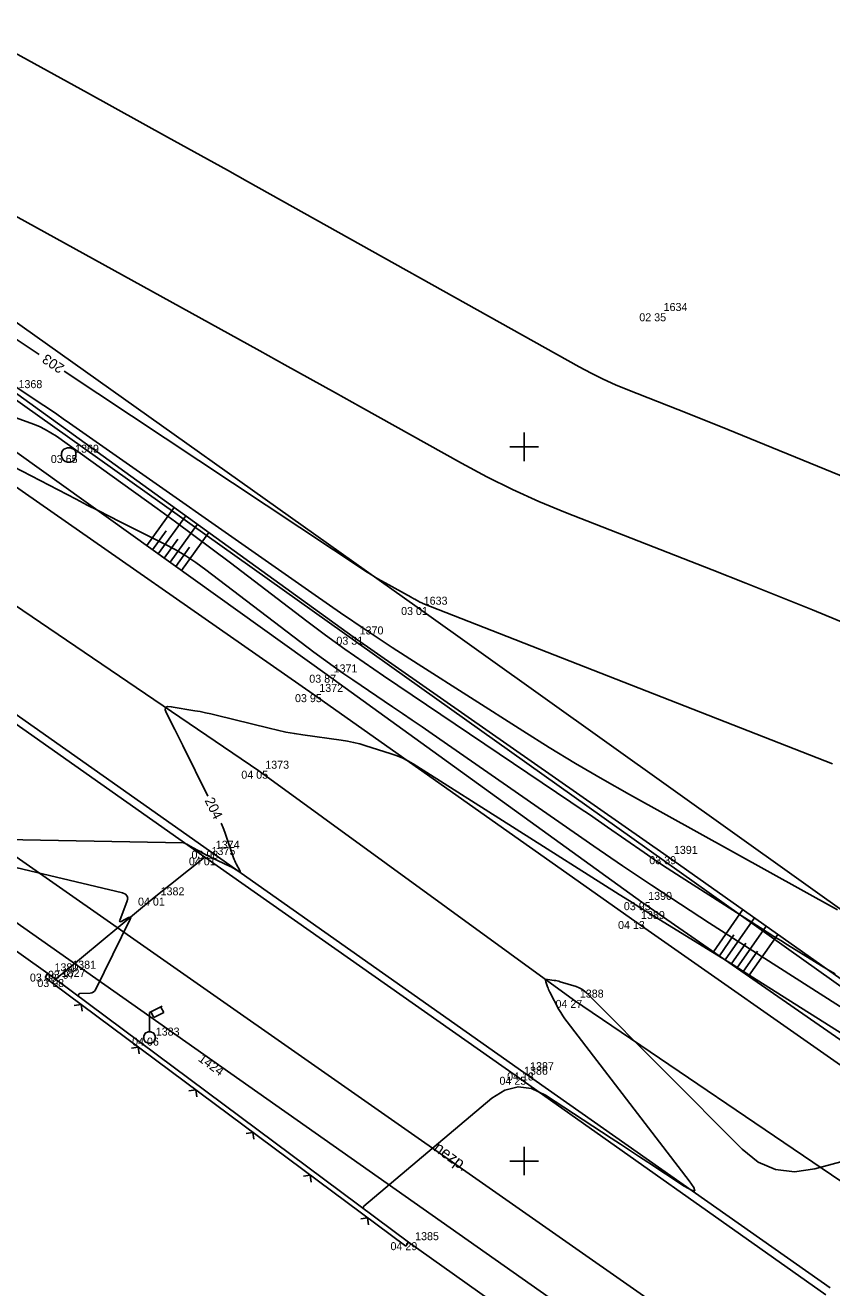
# Model space of a CAD drawing. Extents: x -711234 to -710007, y -1026313 to -1025448.
# Drawn here: x -710542.44 to -710514.24, y -1025579.43 to -1025535.25 of the extents above; entities that cross this region are included whole.
import ezdxf

# ---------------------------------------------------------------- set-up
doc = ezdxf.new("R2010")
doc.units = 0
for name, color, linetype in [('Ex_Contour Labels', 7, 'Continuous'), ('Ex_Major Contours', 7, 'Continuous'), ('Ex_Minor Contours', 7, 'Continuous'), ('Z_body', 7, 'Continuous'), ('Z_body_cisla', 7, 'Continuous'), ('Z_body_vysky_redukovane', 7, 'Continuous'), ('Z_hektometricka_sit', 7, 'Continuous'), ('Z_hrany_paty', 7, 'Continuous'), ('Z_katastr_cisla_pozemkova', 7, 'Continuous'), ('Z_katastr_hranice', 7, 'Continuous'), ('Z_komunikace', 7, 'Continuous'), ('Z_komunikace_osa', 7, 'Continuous'), ('Z_obruba', 7, 'Continuous'), ('Z_ploty', 7, 'Continuous'), ('Z_ploty_znacky', 7, 'Continuous'), ('Z_pole_rozhranni', 7, 'Continuous'), ('Z_popisy', 7, 'Continuous'), ('Z_rozhranni', 7, 'Continuous'), ('Z_site_kanalizace_znaky', 7, 'Continuous'), ('Z_site_vo_znaky', 7, 'Continuous'), ('Z_technicke_srafy', 7, 'Continuous'), ('Z_vstupy', 7, 'Continuous')]:
    doc.layers.add(name, color=color, linetype=linetype)

# ---------------------------------------------------------------- blocks, each defined once
blk = doc.blocks.new('POINT_DISPLAY')
blk.add_line((0, 0), (0, 0))
blk = doc.blocks.new('Z13')
for p, q in [((0, 0.88), (0.45, 1.1)), ((0.15, 0.7), (0.05, 0.9)), ((0.4, 1.07), (0.5, 0.88)), ((0, 0.2), (0, 0.88)), ((0.5, 0.88), (0.15, 0.7)), ((-0.2, 0.05), (-0.15, 0.15)), ((-0.2, -0.05), (-0.2, 0.05)), ((-0.15, 0.15), (-0.05, 0.2)), ((-0.05, 0.2), (0.05, 0.2)), ((0.05, 0.2), (0.15, 0.15)), ((0.15, 0.15), (0.2, 0.05)), ((0.2, 0.05), (0.2, -0.05)), ((-0.15, -0.15), (-0.2, -0.05)), ((-0.05, -0.2), (-0.15, -0.15)), ((0.05, -0.2), (-0.05, -0.2)), ((0.15, -0.15), (0.05, -0.2)), ((0.2, -0.05), (0.15, -0.15))]:
    blk.add_line(p, q)
blk = doc.blocks.new('Z212')
for p, q in [((-0.17, 0.17), (0, 0)), ((0, 0), (0.17, 0.17))]:
    blk.add_line(p, q)
blk = doc.blocks.new('Z620')
for p, q in [((-0.25, 0.05), (-0.23, 0.13)), ((-0.25, -0.05), (-0.25, 0.05)), ((-0.23, 0.13), (-0.17, 0.2)), ((-0.17, 0.2), (-0.05, 0.25)), ((-0.05, 0.25), (0.05, 0.25)), ((0.05, 0.25), (0.17, 0.2)), ((0.17, 0.2), (0.23, 0.13)), ((0.23, 0.13), (0.25, 0.05)), ((0.25, 0.05), (0.25, -0.05)), ((-0.2, -0.17), (-0.25, -0.05)), ((-0.13, -0.23), (-0.2, -0.17)), ((-0.05, -0.25), (-0.13, -0.23)), ((0.05, -0.25), (-0.05, -0.25)), ((0.13, -0.23), (0.05, -0.25)), ((0.2, -0.17), (0.13, -0.23)), ((0.25, -0.05), (0.2, -0.17))]:
    blk.add_line(p, q)

msp = doc.modelspace()

# ---------------------------------------------------------------- linework, layer by layer
at = {"layer": 'Ex_Major Contours'}
for points in [[(-710544.313, -1025545.208), (-710541.957, -1025546.772)], [(-710541.082, -1025547.353), (-710530.483, -1025554.386), (-710530.329, -1025554.486), (-710530.172, -1025554.584), (-710530.013, -1025554.677), (-710529.853, -1025554.768), (-710528.952, -1025555.265), (-710528.918, -1025555.284), (-710528.884, -1025555.303), (-710528.85, -1025555.322), (-710528.816, -1025555.341), (-710528.68, -1025555.416), (-710528.646, -1025555.435), (-710528.612, -1025555.452), (-710528.576, -1025555.468), (-710528.54, -1025555.483), (-710515.021, -1025560.786), (-710514.219, -1025561.103)], [(-710536.055, -1025562.233), (-710536.93, -1025560.46), (-710537, -1025560.318), (-710537.071, -1025560.177), (-710537.143, -1025560.035), (-710537.215, -1025559.894), (-710537.505, -1025559.33), (-710537.548, -1025559.21), (-710537.535, -1025559.132), (-710537.465, -1025559.095), (-710537.337, -1025559.101), (-710536.517, -1025559.238), (-710536.328, -1025559.271), (-710536.141, -1025559.308), (-710535.954, -1025559.349), (-710535.768, -1025559.394), (-710533.911, -1025559.855), (-710533.62, -1025559.924), (-710533.327, -1025559.985), (-710533.033, -1025560.038), (-710532.737, -1025560.083), (-710531.398, -1025560.27), (-710531.178, -1025560.305), (-710530.961, -1025560.35), (-710530.745, -1025560.403), (-710530.531, -1025560.465), (-710529.68, -1025560.732), (-710529.471, -1025560.805), (-710529.267, -1025560.892), (-710529.07, -1025560.991), (-710528.878, -1025561.104), (-710521.67, -1025565.667), (-710521.309, -1025565.895), (-710520.948, -1025566.121), (-710520.586, -1025566.346), (-710520.223, -1025566.57), (-710518.771, -1025567.464), (-710518.408, -1025567.688), (-710518.046, -1025567.912), (-710517.685, -1025568.139), (-710517.324, -1025568.366), (-710507.868, -1025574.338)], [(-710545.031, -1025563.71), (-710536.925, -1025563.86), (-710536.904, -1025563.862), (-710536.883, -1025563.866), (-710536.864, -1025563.873), (-710536.845, -1025563.883), (-710536.772, -1025563.927), (-710536.753, -1025563.938), (-710536.735, -1025563.948), (-710536.716, -1025563.959), (-710536.697, -1025563.969), (-710536.264, -1025564.207), (-710536.185, -1025564.25), (-710536.106, -1025564.291), (-710536.026, -1025564.331), (-710535.945, -1025564.371), (-710535.283, -1025564.688), (-710535.243, -1025564.707), (-710535.203, -1025564.728), (-710535.165, -1025564.75), (-710535.127, -1025564.773), (-710534.976, -1025564.868), (-710534.946, -1025564.884), (-710534.93, -1025564.884), (-710534.929, -1025564.869), (-710534.943, -1025564.837), (-710535.067, -1025564.604), (-710535.093, -1025564.552), (-710535.118, -1025564.498), (-710535.14, -1025564.444), (-710535.159, -1025564.388), (-710535.412, -1025563.63), (-710535.463, -1025563.486), (-710535.518, -1025563.344), (-710535.579, -1025563.204), (-710535.592, -1025563.176)], [(-710540.593, -1025569.224), (-710540.574, -1025569.163), (-710540.57, -1025569.154), (-710540.564, -1025569.147), (-710540.556, -1025569.143), (-710540.546, -1025569.142), (-710540.177, -1025569.126), (-710540.116, -1025569.116), (-710540.065, -1025569.092), (-710540.022, -1025569.055), (-710539.989, -1025569.003), (-710538.769, -1025566.538), (-710538.75, -1025566.49), (-710538.754, -1025566.465), (-710538.779, -1025566.462), (-710538.827, -1025566.482), (-710539.06, -1025566.605), (-710539.108, -1025566.624), (-710539.135, -1025566.621), (-710539.142, -1025566.594), (-710539.128, -1025566.544), (-710538.887, -1025565.927), (-710538.86, -1025565.816), (-710538.879, -1025565.727), (-710538.941, -1025565.662), (-710539.047, -1025565.619), (-710545.09, -1025564.173)]]:
    msp.add_lwpolyline(points, dxfattribs=at)
at = {"layer": 'Ex_Minor Contours'}
for points in [[(-710543.059, -1025536.078), (-710542.36, -1025536.464), (-710541.661, -1025536.849), (-710540.962, -1025537.234), (-710540.263, -1025537.62), (-710537.467, -1025539.162), (-710536.768, -1025539.548), (-710536.07, -1025539.935), (-710535.372, -1025540.323), (-710534.675, -1025540.712), (-710523.071, -1025547.206), (-710522.657, -1025547.429), (-710522.235, -1025547.637), (-710521.807, -1025547.831), (-710521.372, -1025548.01), (-710519.619, -1025548.698), (-710519.181, -1025548.871), (-710518.743, -1025549.045), (-710518.307, -1025549.222), (-710517.871, -1025549.399), (-710509.81, -1025552.704)], [(-710490.545, -1025566.606), (-710501.528, -1025561.382), (-710502.96, -1025560.713), (-710504.4, -1025560.064), (-710505.849, -1025559.435), (-710507.306, -1025558.825), (-710513.755, -1025556.182), (-710514.918, -1025555.708), (-710516.083, -1025555.238), (-710517.249, -1025554.773), (-710518.417, -1025554.312), (-710523.552, -1025552.297), (-710524.484, -1025551.913), (-710525.402, -1025551.498), (-710526.304, -1025551.052), (-710527.192, -1025550.575), (-710530.715, -1025548.603), (-710531.596, -1025548.111), (-710532.478, -1025547.62), (-710533.36, -1025547.131), (-710534.244, -1025546.643), (-710543.487, -1025541.545)], [(-710542.865, -1025547.848), (-710541.788, -1025548.563), (-710541.562, -1025548.714), (-710541.338, -1025548.866), (-710541.114, -1025549.02), (-710540.891, -1025549.175), (-710532.309, -1025555.195), (-710531.417, -1025555.814), (-710530.519, -1025556.423), (-710529.614, -1025557.022), (-710528.702, -1025557.611), (-710525.043, -1025559.949), (-710524.124, -1025560.526), (-710523.197, -1025561.089), (-710522.26, -1025561.637), (-710521.316, -1025562.171), (-710514.038, -1025566.212)], [(-710514.119, -1025568.447), (-710514.361, -1025568.308), (-710514.601, -1025568.167), (-710514.839, -1025568.021), (-710515.787, -1025567.433), (-710516.024, -1025567.285), (-710516.26, -1025567.137), (-710516.496, -1025566.988), (-710516.731, -1025566.838), (-710519.511, -1025565.064), (-710519.837, -1025564.854), (-710520.161, -1025564.64), (-710520.483, -1025564.423), (-710520.802, -1025564.203), (-710522.077, -1025563.318), (-710522.396, -1025563.097), (-710522.716, -1025562.877), (-710523.037, -1025562.659), (-710523.359, -1025562.441), (-710529.916, -1025558.024), (-710530.597, -1025557.557), (-710531.271, -1025557.081), (-710531.938, -1025556.596), (-710532.598, -1025556.1), (-710535.265, -1025554.065), (-710535.901, -1025553.583), (-710536.542, -1025553.105), (-710537.185, -1025552.632), (-710537.833, -1025552.164), (-710541.355, -1025549.636), (-710541.545, -1025549.51), (-710541.741, -1025549.397), (-710541.945, -1025549.298), (-710542.157, -1025549.213), (-710543.017, -1025548.901)], [(-710513.128, -1025570.111), (-710518.515, -1025566.672), (-710519.535, -1025566.014), (-710520.549, -1025565.345), (-710521.556, -1025564.667), (-710522.557, -1025563.979), (-710528.219, -1025560.046), (-710528.564, -1025559.807), (-710528.909, -1025559.57), (-710529.255, -1025559.334), (-710529.602, -1025559.099), (-710530.992, -1025558.163), (-710531.338, -1025557.927), (-710531.68, -1025557.685), (-710532.018, -1025557.438), (-710532.353, -1025557.187), (-710536.124, -1025554.309), (-710536.473, -1025554.056), (-710536.832, -1025553.82), (-710537.202, -1025553.601), (-710537.583, -1025553.399), (-710539.128, -1025552.626), (-710539.513, -1025552.432), (-710539.898, -1025552.237), (-710540.283, -1025552.04), (-710540.666, -1025551.841), (-710543.819, -1025550.2)], [(-710530.634, -1025576.652), (-710530.62, -1025576.609), (-710530.617, -1025576.602), (-710530.614, -1025576.596), (-710530.61, -1025576.59), (-710530.604, -1025576.585), (-710526.125, -1025572.805), (-710525.672, -1025572.515), (-710525.209, -1025572.4), (-710524.735, -1025572.459), (-710524.251, -1025572.693), (-710521.953, -1025574.203), (-710521.633, -1025574.413), (-710521.314, -1025574.623), (-710520.994, -1025574.832), (-710520.675, -1025575.042), (-710519.396, -1025575.88), (-710519.145, -1025576.025), (-710519.033, -1025576.042), (-710519.059, -1025575.931), (-710519.222, -1025575.692), (-710523.497, -1025570.132), (-710523.575, -1025570.027), (-710523.647, -1025569.919), (-710523.716, -1025569.807), (-710523.779, -1025569.693), (-710524.102, -1025569.086), (-710524.124, -1025569.043), (-710524.144, -1025568.998), (-710524.162, -1025568.953), (-710524.179, -1025568.908), (-710524.24, -1025568.723), (-710524.248, -1025568.684), (-710524.239, -1025568.657), (-710524.215, -1025568.644), (-710524.175, -1025568.644), (-710523.947, -1025568.676), (-710523.894, -1025568.685), (-710523.84, -1025568.696), (-710523.788, -1025568.709), (-710523.735, -1025568.724), (-710523.183, -1025568.897), (-710523.077, -1025568.937), (-710522.979, -1025568.989), (-710522.887, -1025569.053), (-710522.803, -1025569.128), (-710517.372, -1025574.587), (-710516.812, -1025575.034), (-710516.203, -1025575.297), (-710515.544, -1025575.376), (-710514.835, -1025575.272), (-710511.75, -1025574.448)]]:
    msp.add_lwpolyline(points, dxfattribs=at)
at = {"layer": 'Z_hektometricka_sit'}
for p, q in [((-710525, -1025549.5), (-710525, -1025550.5)), ((-710525.5, -1025550), (-710524.5, -1025550)), ((-710525, -1025574.5), (-710525, -1025575.5)), ((-710525.5, -1025575), (-710524.5, -1025575))]:
    msp.add_line(p, q, dxfattribs=at)
at = {"layer": 'Z_hrany_paty'}
for p, q in [((-710542.91, -1025548.02), (-710530.98, -1025556.65)), ((-710543.91, -1025549.37), (-710531.88, -1025557.98)), ((-710530.98, -1025556.65), (-710519.99, -1025564.33)), ((-710531.88, -1025557.98), (-710520.88, -1025565.94)), ((-710519.99, -1025564.33), (-710504.65, -1025575.2)), ((-710520.88, -1025565.94), (-710505.57, -1025576.58))]:
    msp.add_line(p, q, dxfattribs=at)
at = {"layer": 'Z_katastr_hranice'}
msp.add_line((-710521.34, -1025581.73), (-710570.34, -1025547.25), dxfattribs=at)
for points in [[(-710600.21, -1025504.82), (-710580.45, -1025521.54), (-710492.86, -1025583.88), (-710429.93, -1025627.5), (-710391.58, -1025654.85), (-710379.57, -1025662.83), (-710367.07, -1025673.36), (-710347.9, -1025691.71), (-710333.8, -1025705.97), (-710271.15, -1025774.38), (-710237.36, -1025811.14)], [(-710507.35, -1025589.15), (-710543.35, -1025563.94), (-710568.66, -1025545.73)]]:
    msp.add_lwpolyline(points, dxfattribs=at)
at = {"layer": 'Z_komunikace'}
for p, q in [((-710544.32, -1025550.33), (-710532.38, -1025558.66)), ((-710548.23, -1025555.52), (-710536, -1025564.14)), ((-710532.38, -1025558.66), (-710521.13, -1025566.6)), ((-710536, -1025564.14), (-710525.01, -1025571.9)), ((-710521.13, -1025566.6), (-710505.98, -1025577.22)), ((-710525.01, -1025571.9), (-710514.29, -1025579.44))]:
    msp.add_line(p, q, dxfattribs=at)
at = {"layer": 'Z_komunikace_osa'}
for p, q in [((-710546.41, -1025553.09), (-710534.28, -1025561.34)), ((-710534.28, -1025561.34), (-710523.27, -1025569.36)), ((-710523.27, -1025569.36), (-710507.82, -1025579.85))]:
    msp.add_line(p, q, dxfattribs=at)
at = {"layer": 'Z_obruba'}
for p, q in [((-710548.43, -1025555.72), (-710536.16, -1025564.37)), ((-710536.16, -1025564.37), (-710525.23, -1025572.05)), ((-710525.23, -1025572.05), (-710514.45, -1025579.68))]:
    msp.add_line(p, q, dxfattribs=at)
at = {"layer": 'Z_ploty'}
for p, q in [((-710541.75, -1025568.58), (-710541.65, -1025568.44)), ((-710541.75, -1025568.58), (-710541.49, -1025568.77)), ((-710541.65, -1025568.44), (-710541.39, -1025568.63)), ((-710541.39, -1025568.63), (-710529.04, -1025577.84)), ((-710541.49, -1025568.77), (-710529.14, -1025577.98)), ((-710529.14, -1025577.98), (-710529.04, -1025577.84))]:
    msp.add_line(p, q, dxfattribs=at)
at = {"layer": 'Z_pole_rozhranni'}
for p, q in [((-710545.97, -1025543.37), (-710528.74, -1025555.61)), ((-710528.74, -1025555.61), (-710510.22, -1025568.84))]:
    msp.add_line(p, q, dxfattribs=at)
at = {"layer": 'Z_rozhranni'}
for p, q in [((-710537.94, -1025565.78), (-710536.16, -1025564.37)), ((-710541.02, -1025568.34), (-710537.94, -1025565.78)), ((-710541.39, -1025568.63), (-710541.02, -1025568.34))]:
    msp.add_line(p, q, dxfattribs=at)
at = {"layer": 'Z_technicke_srafy'}
for p, q in [((-710538.19, -1025553.46), (-710537.23, -1025552.13)), ((-710537.79, -1025553.75), (-710536.83, -1025552.42)), ((-710537.38, -1025554.04), (-710536.42, -1025552.71)), ((-710537.99, -1025553.61), (-710537.51, -1025552.94)), ((-710537.58, -1025553.9), (-710537.11, -1025553.23)), ((-710536.98, -1025554.33), (-710536.02, -1025553)), ((-710537.18, -1025554.19), (-710536.7, -1025553.52)), ((-710518.38, -1025567.68), (-710517.35, -1025566.2)), ((-710517.97, -1025567.96), (-710516.94, -1025566.49)), ((-710517.56, -1025568.25), (-710516.53, -1025566.78)), ((-710518.17, -1025567.82), (-710517.66, -1025567.08)), ((-710517.76, -1025568.11), (-710517.25, -1025567.37)), ((-710517.15, -1025568.53), (-710516.12, -1025567.07)), ((-710517.35, -1025568.39), (-710516.84, -1025567.66))]:
    msp.add_line(p, q, dxfattribs=at)
at = {"layer": 'Z_vstupy'}
for p, q in [((-710546.7, -1025564.86), (-710541.65, -1025568.44)), ((-710529.04, -1025577.84), (-710524.09, -1025581.35))]:
    msp.add_line(p, q, dxfattribs=at)

# ---------------------------------------------------------------- block references
at = {"layer": 'Z_body'}
for p in [(-710520.34, -1025545.33), (-710540.92, -1025550.29), (-710528.74, -1025555.61), (-710530.98, -1025556.65), (-710531.88, -1025557.98), (-710532.38, -1025558.66), (-710534.28, -1025561.34), (-710536, -1025564.14), (-710536.16, -1025564.37), (-710519.99, -1025564.33), (-710537.94, -1025565.78), (-710520.88, -1025565.94), (-710521.13, -1025566.6), (-710541.65, -1025568.44), (-710541.39, -1025568.63), (-710541.02, -1025568.34), (-710523.27, -1025569.36), (-710538.1, -1025570.68), (-710525.23, -1025572.05), (-710525.01, -1025571.9), (-710529.04, -1025577.84)]:
    msp.add_blockref('POINT_DISPLAY', p, dxfattribs=at)
at = {"layer": 'Z_ploty_znacky', "rotation": 143.3}
for p in [(-710540.49, -1025569.52), (-710538.49, -1025571.01), (-710536.48, -1025572.51), (-710534.48, -1025574), (-710532.48, -1025575.5), (-710530.47, -1025576.99)]:
    msp.add_blockref('Z212', p, dxfattribs=at)
at = {"layer": 'Z_site_kanalizace_znaky'}
msp.add_blockref('Z620', (-710540.92, -1025550.29), dxfattribs=at)
at = {"layer": 'Z_site_vo_znaky'}
msp.add_blockref('Z13', (-710538.1, -1025570.68), dxfattribs=at)

# ---------------------------------------------------------------- texts
at = {"layer": 'Ex_Contour Labels'}
for s, rotation, p in [('203', 146.4312, (-710541.046, -1025547.167)), ('204', 296.153, (-710536.18, -1025562.376))]:
    msp.add_text(s, height=0.35, rotation=rotation, dxfattribs=at).set_placement(p)
at = {"layer": 'Z_body_cisla'}
for s, p in [('1634', (-710520.12, -1025545.25)), ('1368', (-710542.68, -1025547.95)), ('1369', (-710540.7, -1025550.21)), ('1633', (-710528.51, -1025555.53)), ('1370', (-710530.75, -1025556.57)), ('1371', (-710531.66, -1025557.9)), ('1372', (-710532.16, -1025558.58)), ('1373', (-710534.05, -1025561.27)), ('1374', (-710535.78, -1025564.07)), ('1375', (-710535.93, -1025564.29)), ('1391', (-710519.76, -1025564.25)), ('1382', (-710537.71, -1025565.7)), ('1390', (-710520.66, -1025565.86)), ('1389', (-710520.91, -1025566.53)), ('1380', (-710541.42, -1025568.36)), ('1827', (-710541.17, -1025568.56)), ('1381', (-710540.8, -1025568.27)), ('1388', (-710523.05, -1025569.28)), ('1383', (-710537.88, -1025570.61)), ('1386', (-710525, -1025571.98)), ('1387', (-710524.79, -1025571.82)), ('1385', (-710528.81, -1025577.77))]:
    msp.add_text(s, height=0.28, dxfattribs=at).set_placement(p)
at = {"layer": 'Z_body_vysky_redukovane'}
for s, p in [('02 35', (-710520.97, -1025545.61)), ('03 65', (-710541.55, -1025550.57)), ('03 01', (-710529.3, -1025555.89)), ('03 31', (-710531.563, -1025556.93)), ('03 87', (-710532.51, -1025558.26)), ('03 95', (-710533.01, -1025558.94)), ('04 05', (-710534.887, -1025561.62)), ('03 98', (-710536.63, -1025564.42)), ('04 01', (-710536.72, -1025564.65)), ('03 39', (-710520.62, -1025564.61)), ('04 01', (-710538.5, -1025566.06)), ('03 95', (-710521.51, -1025566.22)), ('04 13', (-710521.713, -1025566.88)), ('03 98', (-710542.28, -1025568.72)), ('03 98', (-710542.02, -1025568.91)), ('03 97', (-710541.65, -1025568.62)), ('04 27', (-710523.9, -1025569.64)), ('04 06', (-710538.707, -1025570.96)), ('04 25', (-710525.86, -1025572.33)), ('04 18', (-710525.593, -1025572.18)), ('04 29', (-710529.67, -1025578.12))]:
    msp.add_text(s, height=0.28, dxfattribs=at).set_placement(p)
at = {"layer": 'Z_katastr_cisla_pozemkova'}
msp.add_text('1424', height=0.325, rotation=324, dxfattribs=at).set_placement((-710536.422, -1025571.475))
at = {"layer": 'Z_popisy'}
msp.add_text('nezp.', height=0.4, rotation=324, dxfattribs=at).set_placement((-710528.19, -1025574.61))

doc.saveas('drawing.dxf')
